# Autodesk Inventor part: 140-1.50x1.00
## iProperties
Created: 2007-06
Part Number: 140-1.50x1.00
Document SubType Name: Modeling
Designer: btaylor
Density: 1 g/cm^3
Author: btaylor
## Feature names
1. Extrusion1
2. Extrusion2
3. Extrusion3
4. Extrusion4
5. Chamfer1
6. Fillet1
7. Fillet2
8. Chamfer2
9. Fillet3
